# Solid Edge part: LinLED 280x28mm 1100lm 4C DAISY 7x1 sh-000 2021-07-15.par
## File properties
Author: radoslaw.kuczynski
Template: iso metric part.par
Last saved by: radoslaw.kuczynski
Revision: 3
Application: Solid Edge
Gęstość: 0,000 kg/m^3
Dokładność: 0,990
Username: radoslaw.kuczynski
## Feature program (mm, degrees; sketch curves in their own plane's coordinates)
body "unnamed Body 1"
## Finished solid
Body 1: solid body, 1422 faces, 3628 edges, 2280 vertices.
  Faces by surface: plane 838, cylinder 264, spline 192, cone 60, sphere 32, torus 20, spun 16
  Edges by curve: line 2388, curve on surface 644, circle 356, ellipse 132, spline 100, intersection 8
Bounding box of the edges (mm; curved faces can reach further): 279.000 x 4.450 x 28.000, from (-139.5, -3.45, -14) to (139.5, 1, 14).
Cylindrical faces by radius (mm): R0.2 x92, R0.2169 x12, R0.25 x24, R0.3373 x12, R0.4 x16, R0.4006 x4, R0.4008 x4, R0.525 x4, R0.6 x40, R1 x22, R1.1 x8, R1.2 x20, R1.7 x6
Conical faces (half-angle, radius in mm at the cone's reference point): 0.5 deg R0.5056 x8, 0.5 deg R1.0082 x8, 1 deg R0.5511 x4, 10 deg R0.2132 x8, 10 deg R0.4132 x8, 18.8604 deg R1.0669 x8, 27.363 deg R0.6214 x4, 45 deg R0.575 x4, 45 deg R0.625 x8
Toroidal faces (ring radius, tube radius in mm): R0.8 r0.2 x8, R0.8522 r0.3 x4, R0.9002 r0.2 x4, R0.9018 r0.2 x4
Spherical faces by radius (mm): R0.2 x24, R0.6 x8
Planar faces by outward normal: +x 57, +y 17, +z 61, -x 57, -y 133, -z 61, oblique 452
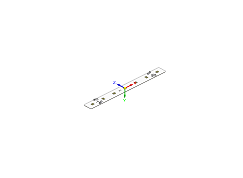
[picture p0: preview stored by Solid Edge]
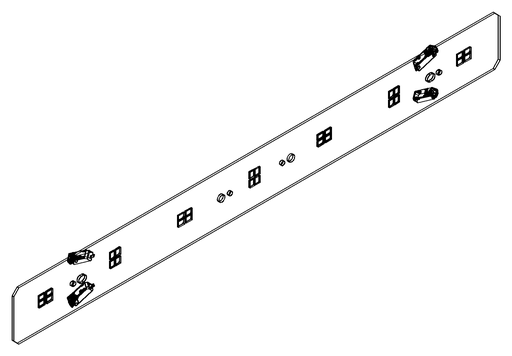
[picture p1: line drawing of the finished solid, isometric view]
